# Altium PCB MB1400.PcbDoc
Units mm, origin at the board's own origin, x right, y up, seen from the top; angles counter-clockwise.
Board outline 25 x 36.5 mm, 4 copper layers (Top Layer, Signal Layer 1, Signal Layer 2, Bottom Layer), stack 1.2 mm thick; 32 components, 21 nets, 197 pads, 102 vias.
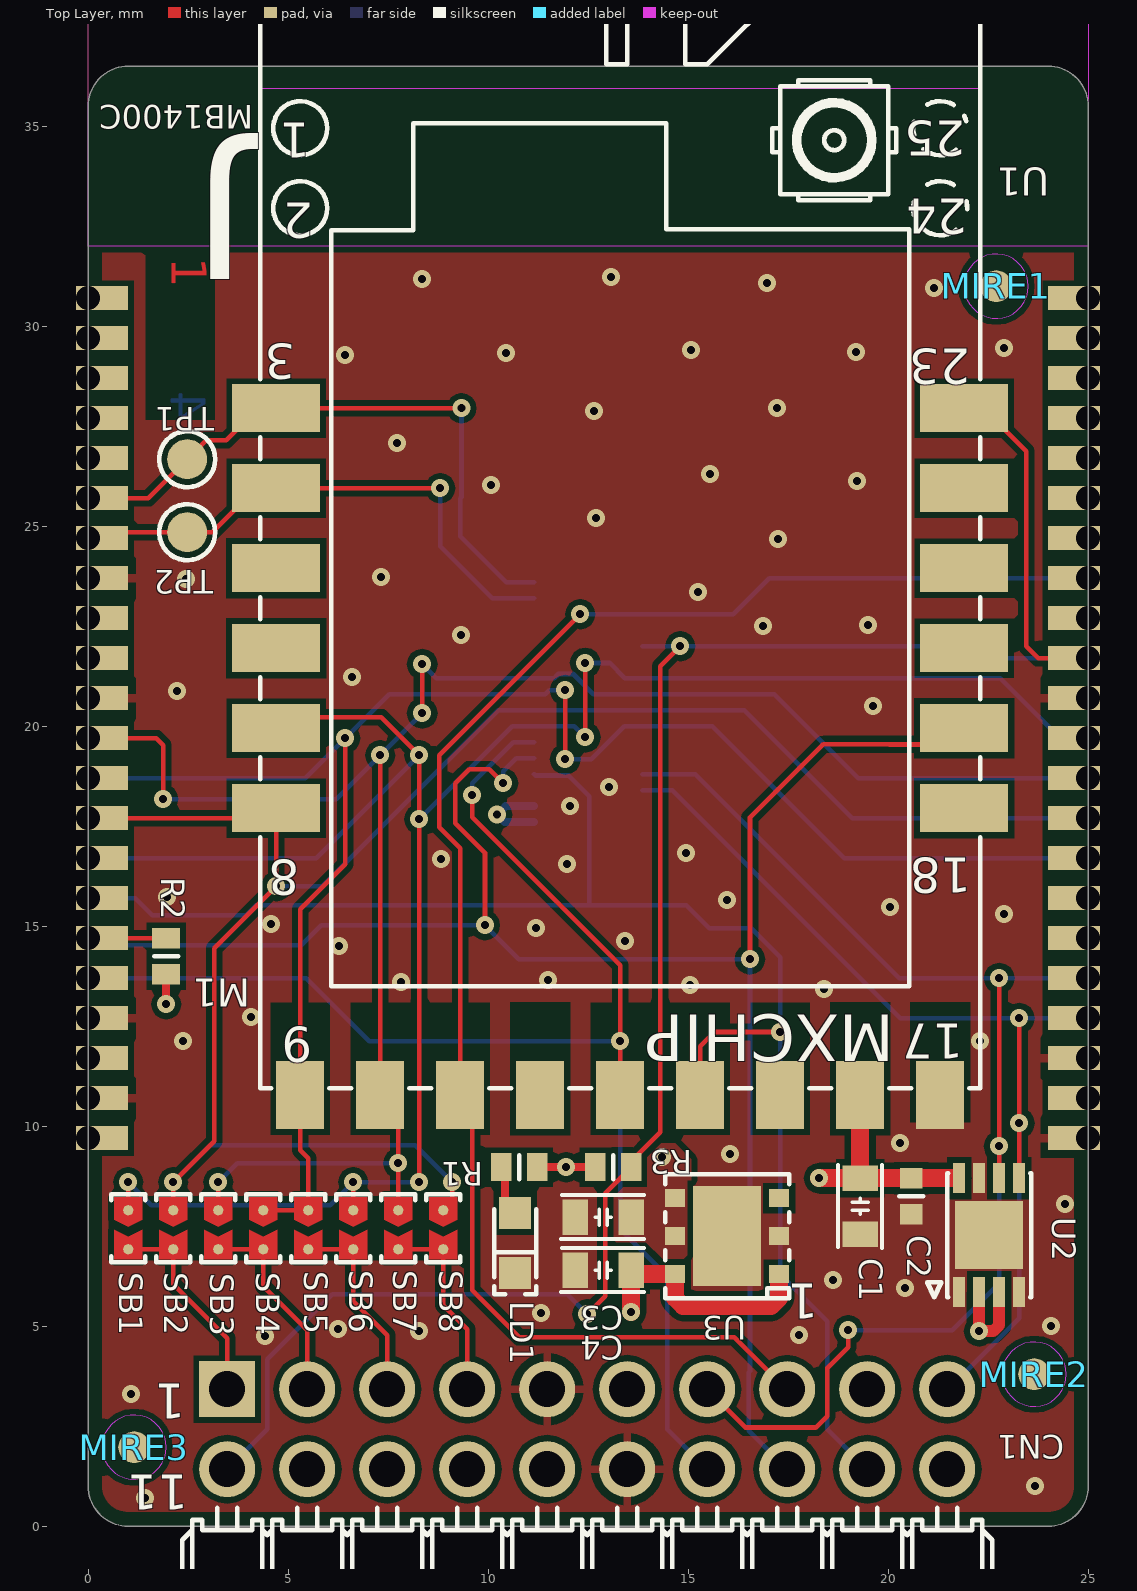
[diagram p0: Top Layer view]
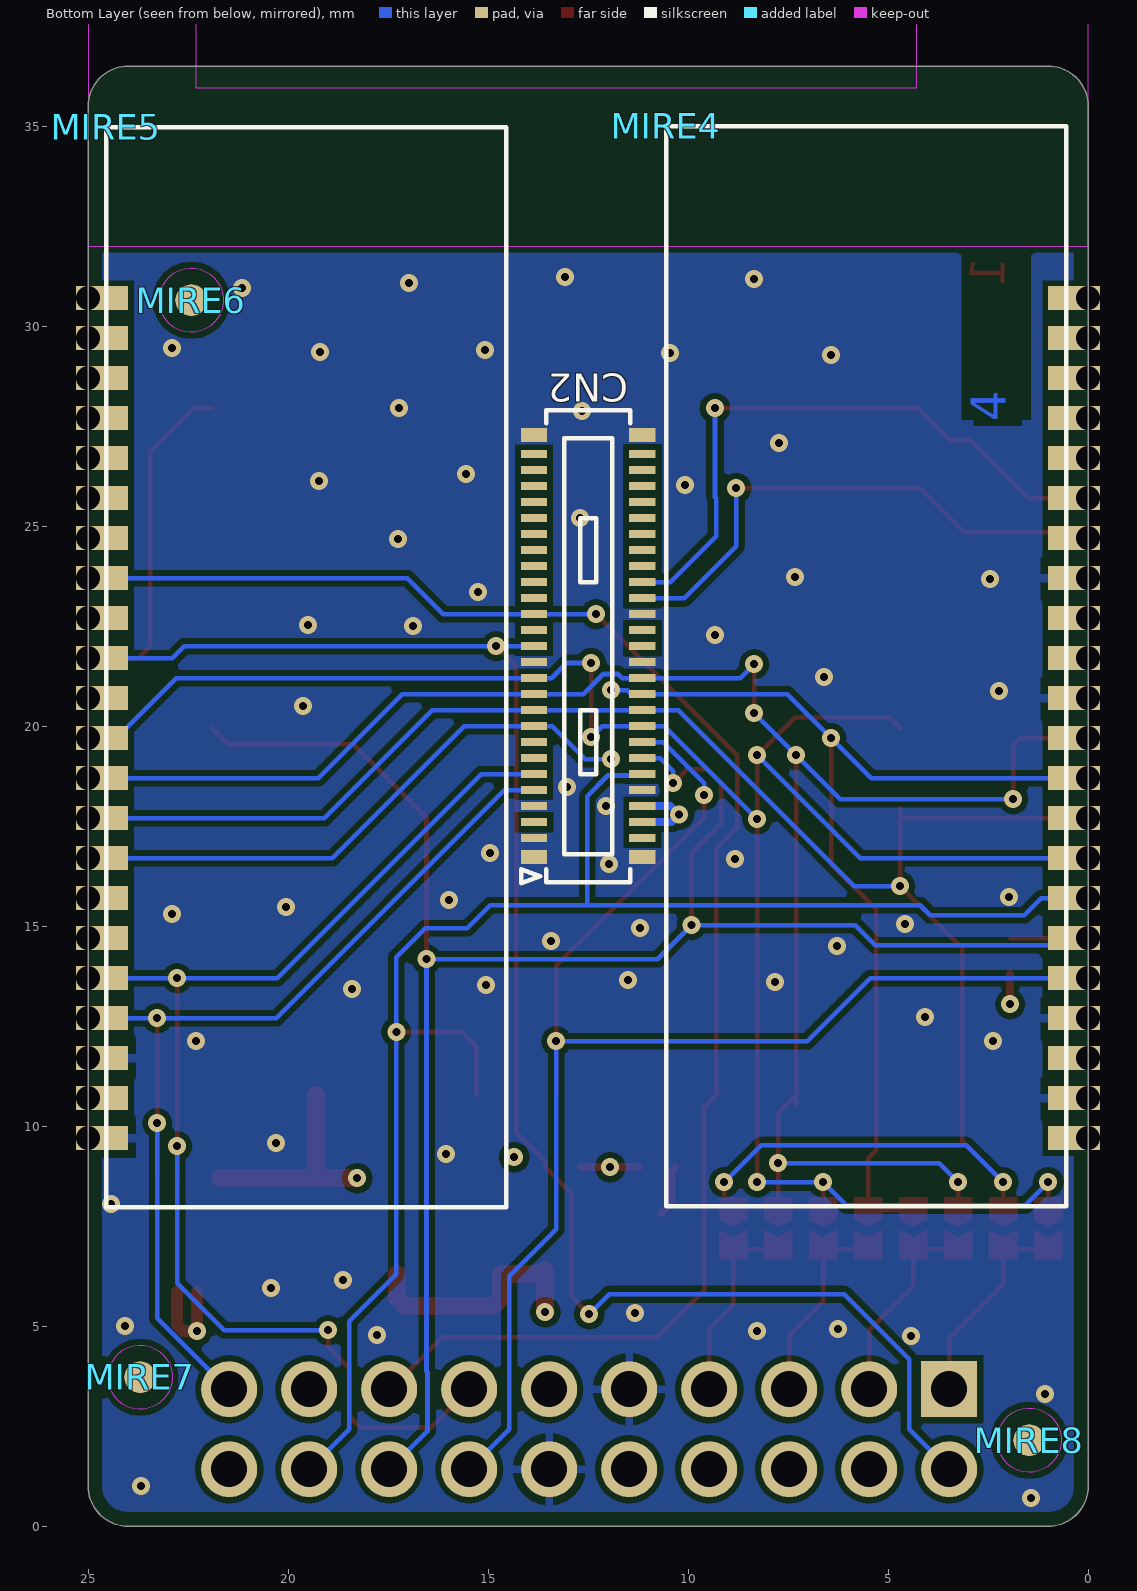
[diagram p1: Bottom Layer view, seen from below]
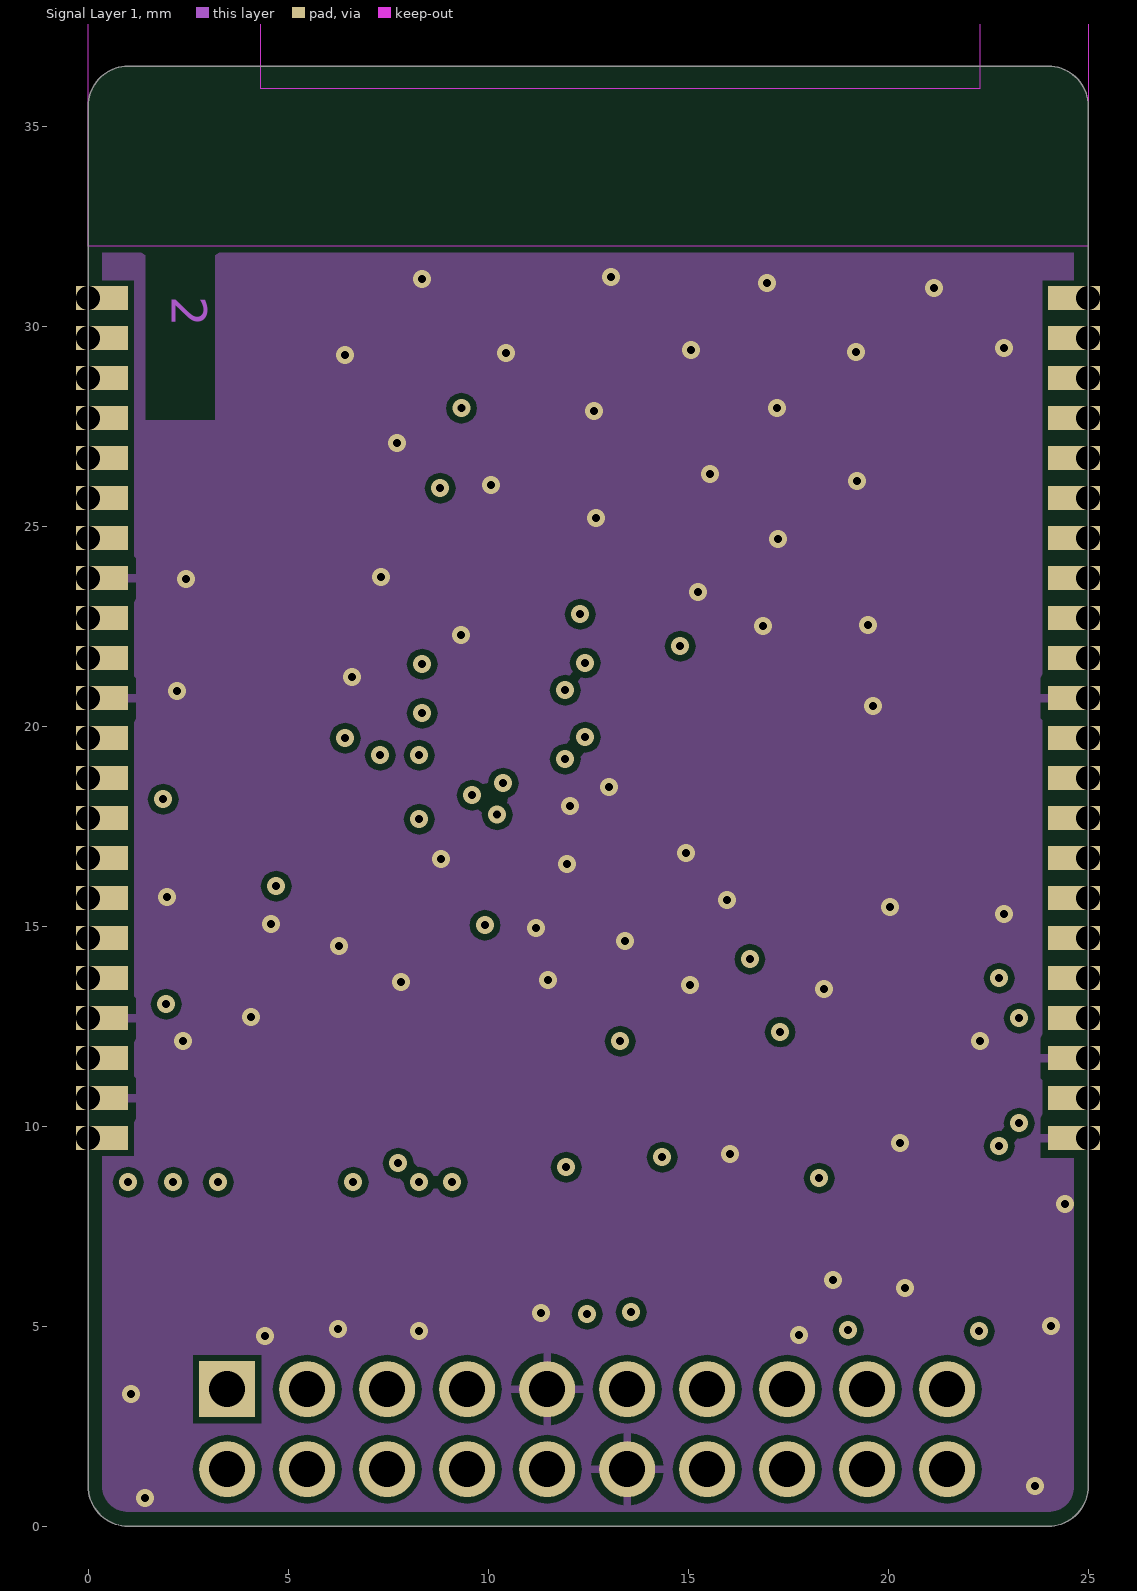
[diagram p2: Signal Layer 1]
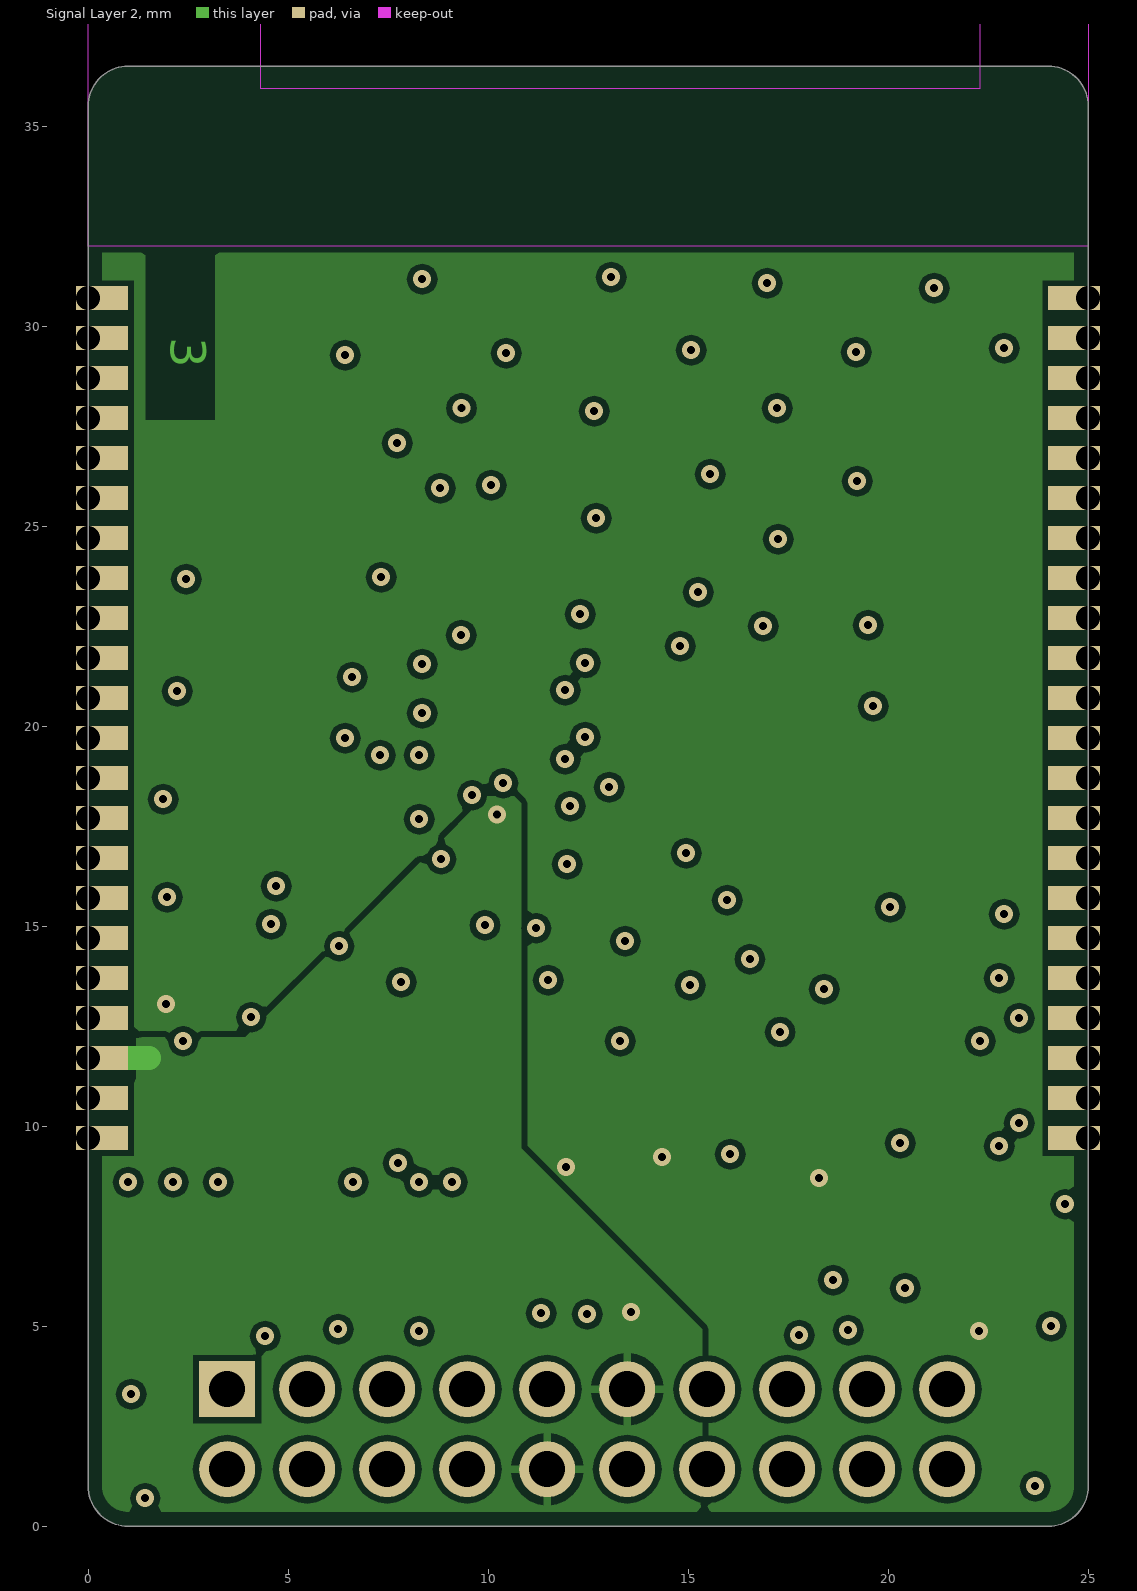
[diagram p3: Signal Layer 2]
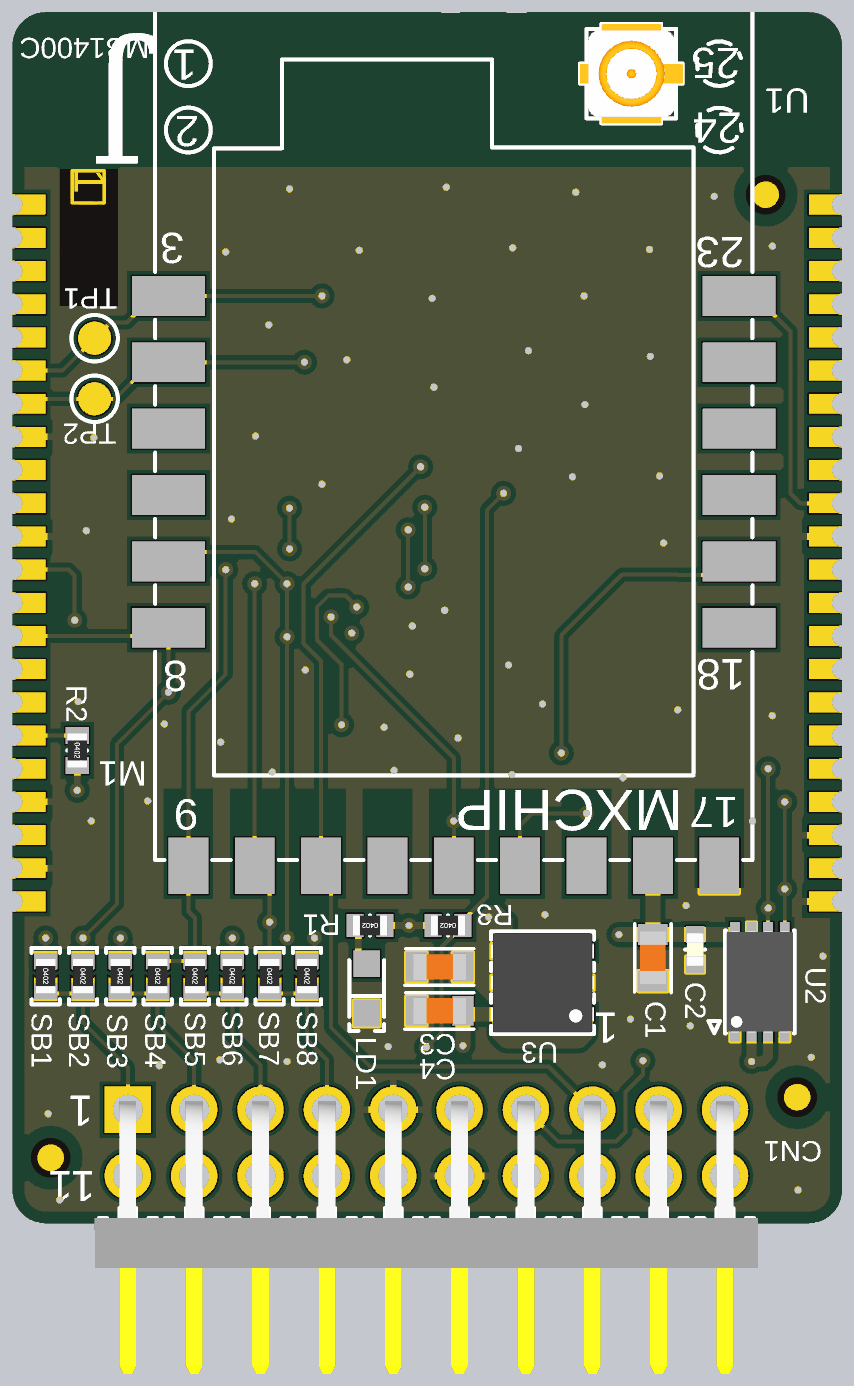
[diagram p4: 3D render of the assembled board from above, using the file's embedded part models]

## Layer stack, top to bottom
Top Solder: solder mask 0.0203, Solder Resist, Dk 3.5
Top Layer: signal copper 0.035
Dielectric 1: core 0.106, FR-4, Dk 4.1
Signal Layer 1: signal copper 0.035
Dielectric 2: prepreg 0.848, Dk 4.25
Signal Layer 2: signal copper 0.035
Dielectric 3: core 0.106, Dk 4.25
Bottom Layer: signal copper 0.035
Bottom Solder: solder mask 0.0203, Solder Resist, Dk 3.5

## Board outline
0,1 0,35.5 cw(c1,35.5) 1,36.5 24,36.5 cw(c24,35.5) 25,35.5 25,1 cw(c24,1) 24,0 1,0 cw(c1,1)

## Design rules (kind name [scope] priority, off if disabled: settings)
BoardOutlineClearance [All] p1: gap=0.4 ignorepadtopadclearanceinfootprint=FALSE except(0.35: Poly-OutlineEdge)
Clearance Clearance_1 [InNetClass('Iso 250µm')] p1: gap=0.25 ignorepadtopadclearanceinfootprint=FALSE except(0: Arc-Hole Track-Hole SMDPad-Hole THPad-Hole Via-Hole Fill-Hole Poly-Hole Region-Hole Text-Hole)
Clearance [All] p2: gap=0.15 ignorepadtopadclearanceinfootprint=FALSE except(0: Arc-Hole Track-Hole SMDPad-Hole THPad-Hole Via-Hole Fill-Hole Poly-Hole Region-Hole Text-Hole; 0.12: Arc-Arc Arc-Track Arc-SMDPad Arc-Via Arc-Text Track-Track Track-SMDPad Track-Via Track-Text SMDPad-Via SMDPad-Text THPad-Via THPad-Text Via-Via Via-Text Fill-Text Poly-Text Region-Text Text-Text; 0.2: Arc-THPad Track-THPad SMDPad-SMDPad SMDPad-THPad THPad-THPad)
ComponentClearance [All] p1 off: gap=0.025 collisioncheckmode=3 verticalgap=2540 showdistances=TRUE
DiffPairsRouting DiffPairsRouting_USB [InDifferentialPairClass('DIFF_USB')] p1: maxlimit=0.12 minlimit=0.12 mostfreqgap=0.12 toplayer_minwidth=0.13 toplayer_maxwidth=0.13 toplayer_prefwidth=0.13 midlayer1_minwidth=0.13 midlayer1_maxwidth=0.13 midlayer1_prefwidth=0.13 midlayer2_minwidth=0.13 midlayer2_maxwidth=0.13 midlayer2_prefwidth=0.13 bottomlayer_minwidth=0.13 bottomlayer_maxwidth=0.13 bottomlayer_prefwidth=0.13 maxuncoupledlength=12.7
FanoutControl Fanout_Default [All] p1: bgadir=Out bgaviamode=Closest fanoutstyle=Auto fanoutdirection=Alternating viagrid=0.025 // Fanout_Default (Default Rule)
HoleSize [All] p1: absolutevalues=TRUE maxlimit=10 minlimit=0.1 maxpercent=80.000 minpercent=20.000
HoleToHoleClearance [All] p1: gap=0.5 allowstackedmicrovias=TRUE
MatchedLengths "MatchedLengths USB diff" [InDifferentialPairClass('All Differential Pairs')] p1: tolerance=0.5 checknetsindiffpair=TRUE checkdiffpairvsdiffpair=FALSE checkxsignals=FALSE checkothers=FALSE
MinimumSolderMaskSliver [All] p1: minsoldermaskwidth=0
PlaneClearance [All] p1: clearance=0.6
PlaneConnect [All] p1: planeconnectstyle=Relief reliefexpansion=0.508 reliefentries=4 reliefconductorwidth=0.254 reliefairgap=0.2
PolygonConnect PolygonConnect_5V [InNet('5V')] p1: thpad.connectstyle=Relief thpad.reliefconductorwidth=0.2 thpad.reliefentries=4 thpad.polygonreliefangle="90 Angle" thpad.airgapwidth=0.2 smdpad.connectstyle=Direct smdpad.reliefconductorwidth=0.254 smdpad.reliefentries=4 smdpad.polygonreliefangle="45 Angle" smdpad.airgapwidth=0.254 via.connectstyle=Direct via.reliefconductorwidth=0.254 via.reliefentries=4 via.polygonreliefangle="45 Angle" via.airgapwidth=0.254
PolygonConnect [All] p2: thpad.connectstyle=Relief thpad.reliefconductorwidth=0.2 thpad.reliefentries=4 thpad.polygonreliefangle="90 Angle" thpad.airgapwidth=0.2 smdpad.connectstyle=Direct smdpad.reliefconductorwidth=0.254 smdpad.reliefentries=4 smdpad.polygonreliefangle="45 Angle" smdpad.airgapwidth=0.254 via.connectstyle=Direct via.reliefconductorwidth=0.254 via.reliefentries=4 via.polygonreliefangle="45 Angle" via.airgapwidth=0.254
RoutingVias [All] p1: holewidth=0.2 width=0.45 viastyle="Through Hole" minholewidth=0.2 minwidth=0.45 maxholewidth=0.2 maxwidth=0.45
SilkToSilkClearance [All] p1: silktosilkclearance=0
SilkToSolderMaskClearance [IsPad] p1: minsilkscreentomaskgap=0 clearancetoexposedcopper=TRUE
SolderMaskExpansion [All] p1: expansion=0.05
Width Width_OSC [InNetClass('Oscillateur')] p1: maxlimit=0.15 minlimit=0.15 preferedwidth=0.15
Width Width_ALIMS [InNetClass('ALIMS')] p2: maxlimit=10 minlimit=0.12 preferedwidth=0.8 minimp=50.000000 maximp=50.000000 favimp=50.000000
Width Width_GND [InNetClass('GND')] p3: maxlimit=10 minlimit=0.12 preferedwidth=0.3 minimp=50.000000 maximp=50.000000 favimp=50.000000
Width [All] p4: maxlimit=10 minlimit=0.12 preferedwidth=0.12 minimp=50.000000 maximp=50.000000 favimp=50.000000
16 further rules are at their usual default settings.

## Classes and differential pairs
polygon class POLY_DIRECT_ALL: NETC906_2_L01_P192

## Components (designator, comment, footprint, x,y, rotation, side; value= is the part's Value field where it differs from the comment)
C1 "Capacitor" C0603 19.3,8 r90 top value=2.2uF
C2 "Capacitor" C0402 20.575,8.25 r90 top value=100nF
C3 "Capacitor" C0603 12.875,7.725 r0 top value=4.7uF
C4 "Capacitor" C0603 12.875,6.4 r0 top value=4.7uF
CN1 "Header 10x2 STMod+" CON_SAMTEC_TMM-110-01-L-D-RA__STMOD+ 12.475,0.155 r0 top
CN2 "DF40C-50DP-0.4V(51)" CON_HRS_DF40C-50DP-0.4V_51 12.5,22 r270 bottom
LD1 "LED_green" LED_0603_VISHAY_VLMTG1300-GS08_GREEN_1A2K_H0P8 10.675,7.075 r270 top value="TRUE GREEN"
M1 "EMW3080(BP)" MOD_WIFI_MXCHIP_EMW3080-BP 13.3,10.95 r0 top
MIRE1 "Comment" MIRE_PLACE_SMD_0P8MM 22.7,31 r0 top
MIRE2 "Comment" MIRE_PLACE_SMD_0P8MM 23.65,3.8 r0 top
MIRE3 "Comment" MIRE_PLACE_SMD_0P8MM 1.15,1.975 r0 top
MIRE4 "Comment" LOGO_ETIQUETTE 10.55,35 r270 bottom locked
MIRE5 "Comment" LOGO_ETIQUETTE 24.55,34.975 r270 bottom
MIRE6 "Comment" MIRE_PLACE_SMD_0P8MM 22.425,30.65 r180 bottom
MIRE7 "Comment" MIRE_PLACE_SMD_0P8MM 23.7,3.725 r180 bottom
MIRE8 "Comment" MIRE_PLACE_SMD_0P8MM 1.475,2.15 r180 bottom
R1 "Resistor" R0402 10.775,8.975 r180 top value=510R
R2 "Resistor" R0402 1.95,14.25 r270 top value=10K
R3 "Resistor" R0402 13.125,8.975 r180 top value=10K
SB1 "SB_ON" SOLDER-BRIDGE_R0402-0R 1,7.45 r270 top
SB2 "SB_ON" SOLDER-BRIDGE_R0402-0R 2.125,7.45 r270 top
SB3 "SB_ON" SOLDER-BRIDGE_R0402-0R 3.25,7.45 r270 top
SB4 "SB_ON" SOLDER-BRIDGE_R0402-0R 4.375,7.45 r270 top
SB5 "SB_ON" SOLDER-BRIDGE_R0402-0R 5.5,7.45 r270 top
SB6 "SB_ON" SOLDER-BRIDGE_R0402-0R 6.625,7.45 r270 top
SB7 "SB_ON" SOLDER-BRIDGE_R0402-0R 7.75,7.45 r270 top
SB8 "SB_ON" SOLDER-BRIDGE_R0402-0R 8.875,7.45 r270 top
TP1 "Test Point" TP_SMD_1MM 2.475,26.675 r90 top
TP2 "Test Point" TP_SMD_1MM 2.475,24.85 r90 top
U1 "WIFI MODULE INTERPOSER" CON_MOD2BOARD_WIFI_MURATA_LBEE5PA1LD 12.5,22 r0 top locked value="WIFI INTERPOSER CONNECTOR"
U2 "M24128-DFMC6TP" ICC_DFN8-EPAD_2X3_P050 22.525,7.275 r180 top value=M24256-DFMC6TG
U3 "ST1L05CPU33R" ICC_DFN6-EPAD_3X3_P095 15.975,7.25 r90 top value="ST1L05CPU33R 3.3V 1.3A"

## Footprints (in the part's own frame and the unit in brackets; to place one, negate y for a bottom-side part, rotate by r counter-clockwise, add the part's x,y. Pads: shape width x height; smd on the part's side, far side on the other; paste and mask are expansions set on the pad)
C0402 [mm]
  rect 0.51x0.56 smd mask+0.05: 1(-0.45,0) 2(0.45,0)
  silkscreen extent 0,-0.3 0,0.3, body extent -0.5,-0.3 0.5,0.3, height 0.4
C0603 [mm]
  rect 0.64x0.89 smd mask+0.05: 1(-0.7,0) 2(0.7,0)
  silkscreen extent -1.05,-0.55 1.02,0.55, body extent -0.9,-0.5 0.9,0.5, height 1.4
CON_HRS_DF40C-50DP-0.4V_51 [mm]
  rect 0.2x0.66 smd mask+0.05: 1(4.8,-1.355) 2(4.4,-1.355) 3(4,-1.355) 4(3.6,-1.355) 5(3.2,-1.355) 6(2.8,-1.355) 7(2.4,-1.355) 8(2,-1.355) 9(1.6,-1.355) 10(1.2,-1.355) 11(0.8,-1.355) 12(0.4,-1.355) 13(0,-1.355) 14(-0.4,-1.355) 15(-0.8,-1.355) 16(-1.2,-1.355) 17(-1.6,-1.355) 18(-2,-1.355) 19(-2.4,-1.355) 20(-2.8,-1.355) 21(-3.2,-1.355) 22(-3.6,-1.355) 23(-4,-1.355) 24(-4.4,-1.355) 25(-4.8,-1.355) 26(-4.8,1.355) 27(-4.4,1.355) 28(-4,1.355) 29(-3.6,1.355) 30(-3.2,1.355) 31(-2.8,1.355) 32(-2.4,1.355) 33(-2,1.355) 34(-1.6,1.355) 35(-1.2,1.355) 36(-0.8,1.355) 37(-0.4,1.355) 38(0,1.355) 39(0.4,1.355) 40(0.8,1.355) 41(1.2,1.355) 42(1.6,1.355) 43(2,1.355) 44(2.4,1.355) 45(2.8,1.355) 46(3.2,1.355) 47(3.6,1.355) 48(4,1.355) 49(4.4,1.355) 50(4.8,1.355)
  rect 0.35x0.66 smd mask+0.05: MT1(5.275,-1.355) MT2(-5.275,-1.355) MT3(-5.275,1.355) MT4(5.275,1.355)
  silkscreen extent -5.9,-1.68 5.92,1.05, body extent -5.9,-1.48 5.9,1.49, height 1.3
CON_MOD2BOARD_WIFI_MURATA_LBEE5PA1LD [mm]
  rect 1.3x0.6 hole 0.6 copper offset -0.35,0 paste-10 mask+0.05: 1(12.5,-12.3) 2(12.5,-11.3) 3(12.5,-10.3) 4(12.5,-9.3) 5(12.5,-8.3) 6(12.5,-7.3) 7(12.5,-6.3) 8(12.5,-5.3) 9(12.5,-4.3) 10(12.5,-3.3) 11(12.5,-2.3) 12(12.5,-1.3) 13(12.5,-0.3) 14(12.5,0.7) 15(12.5,1.7) 16(12.5,2.7) 17(12.5,3.7) 18(12.5,4.7) 19(12.5,5.7) 20(12.5,6.7) 21(12.5,7.7) 22(12.5,8.7)
  rect 1.3x0.6 hole 0.6 copper offset 0.35,0 paste-10 mask+0.05: 23(-12.5,8.7) 24(-12.5,7.7) 25(-12.5,6.7) 26(-12.5,5.7) 27(-12.5,4.7) 28(-12.5,3.7) 29(-12.5,2.7) 30(-12.5,1.7) 31(-12.5,0.7) 32(-12.5,-0.3) 33(-12.5,-1.3) 34(-12.5,-2.3) 35(-12.5,-3.3) 36(-12.5,-4.3) 37(-12.5,-5.3) 38(-12.5,-6.3) 39(-12.5,-7.3) 40(-12.5,-8.3) 41(-12.5,-9.3) 42(-12.5,-10.3) 43(-12.5,-11.3) 44(-12.5,-12.3)
  Keep-Out Layer region: -12.5,20 12.5,20 12.5,10 -12.5,10
CON_SAMTEC_TMM-110-01-L-D-RA__STMOD+ [mm]
  rect 1.4x1.4 hole 0.9 mask+0.05: 1(-9,3.27)
  round 1.4 hole 0.9 mask+0.05: 2(-7,3.27) 3(-5,3.27) 4(-3,3.27) 5(-1,3.27) 6(1,3.27) 7(3,3.27) 8(5,3.27) 9(7,3.27) 10(9,3.27) 11(-9,1.27) 12(-7,1.27) 13(-5,1.27) 14(-3,1.27) 15(-1,1.27) 16(1,1.27) 17(3,1.27) 18(5,1.27) 19(7,1.27) 20(9,1.27)
  silkscreen extent -10.12,-4.7 10.13,0.3, body extent -10.15,-6.35 10.15,3.52, height 4
ICC_DFN6-EPAD_3X3_P095 [mm]
  rect 0.45x0.5 smd mask+0.05: 1(-0.95,-1.3) 2(0,-1.3) 3(0.95,-1.3) 4(0.95,1.3) 5(0,1.3) 6(-0.95,1.3)
  rect 2.5x1.7 smd mask+0.05: EP(0,0)
  silkscreen extent -1.55,-1.55 1.55,1.55, body extent -1.55,-1.55 1.55,1.55, height 1
ICC_DFN8-EPAD_2X3_P050 [mm]
  rect 0.3x0.75 smd mask+0.05: 1(0.75,1.425) 2(0.25,1.425) 3(-0.25,1.425) 4(-0.75,1.425) 5(-0.75,-1.425) 6(-0.25,-1.425) 7(0.25,-1.425) 8(0.75,-1.425)
  rect 1.7x1.7 smd mask+0.05: EP(0,0)
  silkscreen extent -1.05,-1.55 1.55,1.55, body extent -1.05,-1.55 1.05,1.55, height 0.9
LED_0603_VISHAY_VLMTG1300-GS08_GREEN_1A2K_H0P8 [mm]
  rect 0.8x0.8 smd mask+0.05: 1(-0.75,0) 2(0.75,0)
  silkscreen extent -0.85,-0.53 1.28,0.53, body extent -0.85,-0.45 0.85,0.45, height 0.8
LOGO_ETIQUETTE [mm]
  silkscreen extent 0,0 27,10
MIRE_PLACE_SMD_0P8MM [mm]
  round 0.8 smd paste-10 mask+0.2: 1(0,0)
  Top Layer keep-out circle w0.01: c0,0 r0.804
MOD_WIFI_MXCHIP_EMW3080-BP [mm] "MCD-01500"
  rect 2.2x1.2 smd mask+0.05: 3(-8.6,17) 4(-8.6,15) 5(-8.6,13) 6(-8.6,11) 7(-8.6,9) 8(-8.6,7) 18(8.6,7) 19(8.6,9) 20(8.6,11) 21(8.6,13) 22(8.6,15) 23(8.6,17)
  rect 1.2x1.7 smd mask+0.05: 9(-8,-0.175) 10(-6,-0.175) 11(-4,-0.175) 12(-2,-0.175) 13(0,-0.175) 14(2,-0.175) 15(4,-0.175) 16(6,-0.175) 17(8,-0.175)
  Top Layer pour cut-out: -8.75,-0.85 -8.75,2.15 -7.25,2.15 -7.25,-0.85
  Top Layer pour cut-out: -6.75,-0.85 -6.75,2.15 -5.25,2.15 -5.25,-0.85
  Top Layer pour cut-out: -4.75,-0.85 -4.75,2.15 -3.25,2.15 -3.25,-0.85
  Top Layer pour cut-out: -2.75,-0.85 -2.75,2.15 -1.25,2.15 -1.25,-0.85
  Top Layer pour cut-out: -0.75,-0.85 -0.75,2.15 0.75,2.15 0.75,-0.85
  Top Layer pour cut-out: 1.25,-0.85 1.25,2.15 2.75,2.15 2.75,-0.85
  Top Layer pour cut-out: 3.25,-0.85 3.25,2.15 4.75,2.15 4.75,-0.85
  Top Layer pour cut-out: 5.25,-0.85 5.25,2.15 6.75,2.15 6.75,-0.85
  Top Layer pour cut-out: 7.25,-0.85 7.25,2.15 8.75,2.15 8.75,-0.85
  Keep-Out Layer region: 9,33 -9,33 -9,25 9,25
  silkscreen extent -9,0 9,33, body extent -9,0 9,33, height 2.45
R0402 [mm]
  rect 0.51x0.7 smd mask+0.05: 1(-0.45,0) 2(0.45,0)
  silkscreen extent 0,-0.3 0,0.3, body extent -0.52,-0.3 0.52,0.3, height 0.4
SOLDER-BRIDGE_R0402-0R [mil] "MCD-01619"
  round 10 smd paste-393.7: 1(-17.72,0) 2(20.67,0)
  Top Layer region: -30.51,-13.78 -30.51,13.78 -8.37,13.78 -1.48,0 -8.37,-13.78
  Top Layer region: 1.48,13.78 8.37,0 1.48,-13.78 30.51,-13.78 30.51,13.78
  silkscreen extent -33,-17 33,17, body extent -20,-12 20,12, height 14
TP_SMD_1MM [mm]
  round 1 smd paste-10 mask+0.05: 1(0,0)
  silkscreen extent -0.7,-0.7 0.7,0.7

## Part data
C1: library part MCD-00012, "Capacitor, MLCC, 2.2uF, 10V, X5R, 10%, 0603, T=0,8mm", Alternate_Manufacturer=KEMET, Alternate_Manufacturer_Part_Number=C0603C225K8PACTU, Manufacturer=YAGEO, Manufacturer_Part_Number=CC0603KRX5R6BB225, Package=C0603
C2: library part MCD-00006, "Capacitor, MLCC, 100nF, 16V, X7R, 10%, 0402, T=0.5mm", Alternate_Manufacturer=MURATA, Alternate_Manufacturer_Part_Number=GCM155R71C104KA55D, Manufacturer=YAGEO, Manufacturer_Part_Number=CC0402KRX7R7BB104, Package=C0402
C3 C4: library part MCD-00009, "Capacitor, MLCC, 4.7uF, 16V, X5R, 10%, 0603, T=0.8mm", Manufacturer=YAGEO, Manufacturer_Part_Number=CC0603KRX5R7BB475, Package=C0603
CN1: library part MCD-00288, "Header 10x2, 2mm, RA, TH, Height 3.20mm/3.50mm", Alternate_Manufacturer=JIUBABA, Alternate_Manufacturer_Part_Number=PH200210C-07000, Manufacturer=SAMTEC, Manufacturer_Part_Number=TMM-110-01-L-D-RA
CN2: library part MCD-01227, "Header 25x2, 0.4mm pitch, VR, SMT, Height 1.5mm", Manufacturer=HIROSE
LD1: library part MCD-00589, "LED Green, 0603 SMD, Fw Voltage = 2.8V - 3.6V", Alternate_Manufacturer="OSRAM OPTO SEMICONDUCTORS", Alternate_Manufacturer_Part_Number="LG Q396-PS-35", Manufacturer=VISHAY, Manufacturer_Part_Number=VLMTG1300-GS08, Package="LED 0603"
M1: library part MCD-01500, "Wi-Fi module 33x18mm, UART-SPI interface", Manufacturer=MXCHIP
R1: library part MCD-00064, "Resistor,510R,0402,1%,1/16W", Manufacturer=YAGEO, Manufacturer_Part_Number=RC0402FR-07510RL, Package=R0402
R2 R3: library part MCD-00053, "Resistor,10K,0402,1%,1/16W", Manufacturer=YAGEO, Manufacturer_Part_Number=RC0402FR-0710KL, Package=R0402
SB1 SB2 SB3 SB4 SB5 SB6 SB7 SB8: library part MCD-01618, "Solder Bridge 0402 ON", Manufacturer=YAGEO, Manufacturer_Part_Number=RC0402JR-070RL, Package=SB0402
TP1 TP2: library part MCD-00074, "Test Point 1mm", Manufacturer=n/a
U1: library part MCD-01334, "44 pins Generic Interposer Connector (Not Fitted : Footprint only)", Manufacturer=N/A
U2: library part MCD-01871, "I2C Memory 3V3, 256Kbits, 2x3,0.55mm, UFDFPN8", Manufacturer=STMICROELECTRONICS, Manufacturer_Part_Number=M24256-DFMC6TG
U3: library part MCD-01025, "LDO, 3.3V, 1.3A, Very low quiescent current BiCMOS voltage regulator", Manufacturer=STMICROELECTRONICS, Package=DFN6-3x3

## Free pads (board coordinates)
  round 0.508 on Mech16: 1(15.163,-20.715) 1(64.01,-20.715)

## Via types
v1: diameter 0.45, hole 0.2, Top Layer to Bottom Layer, tented both sides, 102 vias

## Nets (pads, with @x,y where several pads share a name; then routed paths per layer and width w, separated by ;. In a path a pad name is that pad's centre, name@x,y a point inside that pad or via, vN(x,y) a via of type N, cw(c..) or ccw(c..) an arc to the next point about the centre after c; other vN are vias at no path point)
5V: C4.2 CN1.6 CN1.15 CN2.48 CN2.49 U1.42 U3.1 U3.6 | length 9.7
  Top Layer w0.45: v1(13.575,5.35) C4.2 13.675,6.3 U3.6 14.675,5.7 14.875,5.5 17.075,5.5 17.275,5.7 U3.1
  Signal Layer 2 w0.6: U1.42 1.525,11.7
  Bottom Layer w0.2: CN2.49 10.412,17.6 v1(10.225,17.788) 10.437,18 CN2.48
BOOT: CN1.18 CN2.45 M1.19 R2.1 U1.39 | length 47.7
  Top Layer w0.12: U1.39@0.46,14.7 R2.1 ; v1(9.918,15.025) 9.918,16.832 9.175,17.575 9.175,18.575 9.525,18.925 10.025,18.925 v1(10.375,18.575) ; v1(16.541,14.175) 16.541,17.716 18.375,19.55 20.027,19.55 20.032,19.545 21.495,19.545 M1.19
  Bottom Layer w0.12: U1.39@0.46,14.7 0.635,14.525 5.325,14.525 5.825,15.025 v1(9.918,15.025) 10.768,14.175 v1(16.541,14.175) 16.541,3.875 16.515,3.849 16.515,2.385 CN1.18 ; v1(10.375,18.575) 10.375,18.875 10.7,19.2 CN2.45
CHIP_EN: CN1.8 CN2.15 M1.11 U1.15 | length 40.2
  Top Layer w0.12: v1(12.3,22.8) 8.775,19.275 8.775,17.475 9.3,16.95 M1.11 9.6,10.475 9.6,5.9 10.775,4.725 16.15,4.725 CN1.8@17.475,3.4
  Bottom Layer w0.12: v1(12.3,22.8) CN2.15 16.125,22.8 17.025,23.7 U1.15@24.54,23.7
ELINK: CN1.11 CN2.13 M1.23 R3.1 U1.13 | length 49.1
  Top Layer w0.12: v1(12.475,5.3) 12.925,5.75 12.925,8.325 R3.1 13.575,9.125 14.3,9.85 14.3,21.5 v1(14.8,22) ; M1.23 22.375,27.95 23.45,26.875 23.45,22 23.75,21.7 U1.13@24.54,21.7
  Bottom Layer w0.12: CN1.11 4.475,2.425 4.475,4.175 6.1,5.8 11.975,5.8 v1(12.475,5.3) ; CN2.13 22.6,22 22.9,21.7 U1.13
FLOW: CN1.17 CN2.44 M1.13 U1.40 | length 36.4
  Top Layer w0.12: v1(9.6,18.275) 9.6,17.725 13.3,14.025 v1(13.3,12.125) M1.13
  Bottom Layer w0.12: U1.40@0.46,13.7 5.45,13.7 7.025,12.125 v1(13.3,12.125) 13.3,7.425 14.475,6.25 14.475,2.425 CN1.17 ; v1(9.6,18.275) 9.6,18.575 10.625,19.6 CN2.44
GND: C1.1 C2.1 C3.1 C4.1 CN1.5 CN1.16 CN2.1 CN2.3 CN2.12 CN2.36 CN2.39 CN2.47 CN2.MT1 CN2.MT2 CN2.MT3 CN2.MT4 LD1.2 M1.17 U1.1 U1.3 U1.12 U1.30 U1.33 U1.41 U1.43 U2.1 U2.4 U2.7 U2.EP U3.2 U3.EP
  other v1: 1.425,0.7 23.675,1 1.075,3.3 4.425,4.75 17.775,4.775 8.275,4.875 6.25,4.925 24.075,5 11.325,5.325 20.425,5.95 18.625,6.15 24.425,8.05 16.05,9.3 20.3,9.575 2.375,12.125 22.3,12.125 4.075,12.725 18.4,13.425 15.05,13.525 7.825,13.6 11.5,13.65 6.275,14.5 13.425,14.625 11.2,14.95 4.575,15.05 22.9,15.3 20.05,15.475 15.975,15.65 1.975,15.725 11.975,16.55 8.825,16.675 14.95,16.825 12.05,18 13.025,18.475 19.625,20.5 2.225,20.875 6.6,21.225 9.325,22.275 16.875,22.5 19.5,22.525 15.25,23.35 2.45,23.675 7.325,23.725 17.25,24.675 12.7,25.2 10.075,26.025 19.225,26.125 15.55,26.3 7.725,27.075 12.65,27.875 17.225,27.95 6.425,29.275 10.45,29.325 19.2,29.35 15.075,29.4 22.9,29.45 21.15,30.95 16.975,31.075 8.35,31.175 13.075,31.225
I2C_SCL: CN1.7 CN2.5 U1.5 U2.6 | length 31.8
  Top Layer w0.12: CN1.7 16.435,2.465 18.19,2.465 18.475,2.75 18.475,3.952 19,4.477 v1(19,4.9) ; U2.6 v1(22.775,9.5) v1(22.775,13.7)
  Bottom Layer w0.12: CN2.5 15.175,18.8 20.275,13.7 U1.5 ; v1(19,4.9) 21.597,4.9 22.775,6.078 v1(22.775,9.5)
I2C_SDA: CN1.10 CN2.4 U1.4 U2.5 | length 24.5
  Top Layer w0.12: U2.5 v1(23.275,10.075) v1(23.275,12.7)
  Bottom Layer w0.12: CN2.4 14.6,18.4 20.3,12.7 U1.4@24.54,12.7 ; CN1.10@21.475,3.4 23.275,5.2 v1(23.275,10.075)
JTCK: CN2.34 M1.3 TP1.1 U1.28 | length 15.8
  Top Layer w0.12: U1.28 1.5,25.7 TP1.1 2.95,27.15 3.45,27.15 4.25,27.95 M1.3 v1(9.33,27.95)
  Bottom Layer w0.12: v1(9.33,27.95) 9.33,25.73 9.3,25.7 9.3,24.75 10.45,23.6 CN2.34
JTMS: CN2.35 M1.4 TP2.1 U1.29 | length 13.7
  Top Layer w0.12: U1.29 0.15,24.85 TP2.1 3.1,24.85 4.2,25.95 M1.4 v1(8.8,25.95)
  Bottom Layer w0.12: v1(8.8,25.95) 8.8,24.5 10.1,23.2 CN2.35
NetCN1_1: CN1.1 SB1.2 SB2.2 | length 5.2
  Top Layer w0.12: SB1.2 SB2.2 2.125,6.05 3.475,4.7 CN1.1
NetCN1_2: CN1.2 SB3.2 SB4.2 | length 5.1
  Top Layer w0.12: SB3.2 SB4.2 4.375,6 5.475,4.9 CN1.2
NetCN1_3: CN1.3 SB5.2 SB6.2 | length 5
  Top Layer w0.12: SB5.2 SB6.2 6.625,5.625 7.475,4.775 CN1.3@7.475,3.4
NetCN1_4: CN1.4 SB7.2 SB8.2 | length 4.9
  Top Layer w0.12: SB7.2 SB8.2 8.875,5.525 9.475,4.925 CN1.4@9.475,3.4
NetLD1_1: LD1.1 R1.2 | length 1.3
  Top Layer w0.2: R1.2 10.425,8.875 10.425,8.075 LD1.1
NOTIFY: CN1.19 CN2.46 M1.14 U1.38 | length 39.5
  Top Layer w0.12: M1.14 15.3,12 15.654,12.354 v1(17.299,12.354)
  Bottom Layer w0.12: U1.38 1.175,15.7 1.6,15.275 3.95,15.275 4.2,15.525 14.95,15.525 15.525,14.95 16.575,14.95 17.299,14.226 17.299,6.301 18.475,5.125 18.475,2.425 CN1.19 ; CN2.46 11.175,18.77 12.005,18.77 12.525,18.25 12.525,15.525
SPI_MISO: CN2.11 CN2.43 M1.7 SB1.1 SB6.1 U1.11 U1.37 | length 52.8
  Top Layer w0.12: SB1.1 v1(1,8.6) ; M1.7 4.975,20.225 7.325,20.225 v1(8.275,19.275) v1(8.275,8.6) ; SB6.1 v1(6.625,8.6) ; v1(12.425,19.725) v1(12.425,21.582)
  Bottom Layer w0.12: U1.37@0.46,16.7 5.7,16.7 v1(8.275,19.275) ; v1(1,8.6) 1.575,8.025 6.05,8.025 v1(6.625,8.6) v1(8.275,8.6) ; v1(8.275,17.675) 10.6,20 CN2.43 12.15,20 v1(12.425,19.725) ; v1(12.425,21.582) 13.036,21.582 13.418,21.2 CN2.11 17.525,21.2 22.8,21.2 24.3,19.7 U1.11@24.54,19.7
SPI_MOSI: CN2.8 CN2.41 M1.9 SB4.1 SB5.1 U1.8 U1.35 | length 42.4
  Top Layer w0.12: SB4.1 SB5.1 5.5,9.2 5.3,9.4 M1.9 5.3,15.425 6.425,16.55 v1(6.425,19.7) ; v1@11.925,19.15 v1(11.925,20.9)
  Bottom Layer w0.12: U1.35@0.46,18.7 5.425,18.7 v1(6.425,19.7) 7.525,20.8 CN2.41 11.425,20.8 11.525,20.9 v1(11.925,20.9) ; v1(11.925,19.175) 12.575,19.175 13.4,20 CN2.8 15.6,20 18.9,16.7 U1.8
SPI_NSS: CN2.9 CN2.42 M1.8 SB2.1 SB8.1 U1.9 U1.36 | length 47.1
  Top Layer w0.12: U1.36@0.46,17.7 M1.8@4.7,17.7 ; SB2.1 v1(2.125,8.6) 3.15,9.625 3.15,14.45 v1(4.7,16) M1.8@4.7,17.7 ; M1.8 M1.8@4.7,17.7 ; SB8.1 9.1,8.125 v1(9.1,8.6)
  Bottom Layer w0.12: v1(2.125,8.6) 3.05,9.525 8.175,9.525 v1(9.1,8.6) ; v1(4.7,16) 5.85,16 10.25,20.4 CN2.42 CN2.9 16.4,20.4 19.1,17.7 U1.9
SPI_SCK: CN2.10 CN2.40 M1.10 SB3.1 SB7.1 U1.10 U1.34 | length 46.5
  Top Layer w0.12: U1.34@0.46,19.7 1.7,19.7 1.875,19.525 v1(1.875,18.175) ; SB3.1 v1(3.25,8.6) ; M1.10@7.3,10.55 M1.10 ; v1(7.3,19.275) M1.10 ; SB7.1 v1(7.75,9.075) 7.75,10.325 M1.10 ; v1(8.35,20.325) v1(8.35,21.55)
  Bottom Layer w0.12: v1(1.875,18.175) 6.2,18.175 v1(7.3,19.275) v1(8.35,20.325) ; v1(3.25,8.6) 3.725,9.075 v1(7.75,9.075) ; v1(8.35,21.55) 8.7,21.2 CN2.40 11.652,21.2 11.757,21.305 12.12,21.305 12.625,20.8 CN2.10 17.15,20.8 19.25,18.7 U1.10
VDD_3V3: C1.2 C2.2 C3.2 M1.16 R1.1 R2.2 R3.2 U2.2 U2.3 U2.8 U3.4 U3.5 | length 10.1
  Top Layer w0.2: v1(1.95,13.05) R2.2 ; R1.1 R3.2
  Top Layer w0.3: U2.2 v1(22.275,4.875) 22.625,4.875 22.775,5.025 U2.3
  Top Layer w0.45: v1(18.275,8.7) C1.2 ; M1.16 C1.2 ; U2.8@21.7,8.7 C2.2 C1.2
  other v1: 11.95,8.975 14.35,9.225
pads on no net: CN1.9 CN1.12 CN1.13 CN1.14 CN1.20 CN2.2 CN2.6 CN2.7 CN2.14 CN2.16 CN2.17 CN2.18 CN2.19 CN2.20 CN2.21 CN2.22 CN2.23 CN2.24 CN2.25 CN2.26 CN2.27 CN2.28 CN2.29 CN2.30 CN2.31 CN2.32 CN2.33 CN2.37 CN2.38 CN2.50 M1.5 M1.6 M1.12 M1.15 M1.18 M1.20 M1.21 M1.22 MIRE1.1 MIRE2.1 MIRE3.1 MIRE6.1 MIRE7.1 MIRE8.1 U1.2 U1.6 U1.7 U1.14 U1.16 U1.17 U1.18 U1.19 U1.20 U1.21 U1.22 U1.23 U1.24 U1.25 U1.26 U1.27 U1.31 U1.32 U1.44 U3.3

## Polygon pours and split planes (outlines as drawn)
5V on Signal Layer 2 "5V" (solid, remove dead copper, pour order 12): 9.95,18.25 10.65,18.25 10.825,18.075 10.825,9.45 15.35,4.925 15.35,0 0,0 0,12.225 3.925,12.225
VDD_3V3 on Signal Layer 2 "VDD_3V3" (solid, pour order 14): 0,0 25,0 25,32 0,32
GND on Top Layer "GND" (solid, remove dead copper, pour order 10): 0,0 25,0 25,32 0,32
VDD_3V3 on Top Layer "VDD_3V3" (solid, remove dead copper, pour order 8): 13.94,7.1 14.358,6.682 14.882,6.682 15.075,6.875 15.075,9.175 14.675,9.575 13.382,9.575 13.1,9.293 13.1,7.2 13.2,7.1
GND on Signal Layer 1 "GND" (solid, pour order 6): 0,32 25,32 25,0 0,0
GND on Bottom Layer "GND" (solid, pour order 18): 0,0 25,0 25,32 0,32

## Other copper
Top Layer:
  text "1" at 1.8,31.725 h1.5 r270
  text ".Layer_Name" at 3.493,-14.367 h3
  text ".GTL" at 45.188,-14.367 h3
Signal Layer 1:
  text "2" at 1.8,30.75 h1.5 r270
  text ".Layer_Name" at 3.493,-14.367 h3
  text ".G1" at 45.188,-14.367 h3
Signal Layer 2:
  text "3" at 1.775,29.725 h1.5 r270
  text ".Layer_Name" at 3.493,-14.367 h3
  text ".G2" at 45.188,-14.367 h3
Bottom Layer:
  text "4" at 1.775,27.625 h1.5 r270
  text ".GBL" at 33.985,-14.399 h3
  text ".Layer_Name" at 75.299,-14.399 h3
Multi-Layer:
  pour cut-out: 1.423,27.65 3.173,27.65 3.173,31.775 1.423,31.775

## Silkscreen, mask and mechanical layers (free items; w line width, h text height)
Top Overlay:
  text "MB1400C" at 4.125,35.725 h1 r180
  text "J" at 4,35 h6 r180
  text ".Layer_Name" at 3.493,-14.367 h3
  text ".GTO" at 45.188,-14.367 h3
Bottom Overlay:
  text ".GBO" at 33.985,-14.399 h3
  text ".Layer_Name" at 75.299,-14.399 h3
Top Paste:
  text ".Layer_Name" at 3.493,-14.367 h3
  text ".GTP" at 45.188,-14.367 h3
Bottom Paste:
  text ".GBP" at 33.985,-14.399 h3
  text ".Layer_Name" at 75.299,-14.399 h3
Top Solder:
  region: 3.173,31.775 1.423,31.775 1.423,27.65 3.173,27.65
  text ".Layer_Name" at 3.493,-14.367 h3
  text ".GTS" at 45.188,-14.367 h3
Bottom Solder:
  region: 3.173,31.775 1.423,31.775 1.423,27.65 3.173,27.65
  text ".GBS" at 33.985,-14.399 h3
  text ".Layer_Name" at 75.299,-14.399 h3
M1-Board Shape:
  the board outline again, w0.1
M2-Board Dimensions:
  text ".Layer_Name" at 3.493,-14.367 h3
  text ".GM2" at 45.188,-14.367 h3
M14-Top Assembly:
  text ".Layer_Name" at 3.493,-14.367 h3
  text ".GM14" at 45.188,-14.367 h3
M15-Bottom Assembly:
  text ".GM15" at 33.985,-14.399 h3
  text ".Layer_Name" at 75.299,-14.399 h3
Drill Drawing:
  drawing of 318 lines, arcs and shapes, not listed
  text "PCB SPECIFICATIONS :" at 60.175,85.9 h3
  text "A.   MATERIAL :" at 60.175,81.9 h3
  text "FR-4" at 98.675,81.9 h3
  text "TG-170" at 115.175,81.9 h3
  text "X  TG-150" at 133.425,81.9 h3
  text "TG-140" at 149.425,81.9 h3
  text "B.   MATERIAL FAMILY :" at 60.175,78.9 h3
  text "N/A" at 98.675,78.9 h3
  text "C.   SOLDERMASK COLOR :" at 60.175,75.9 h3
  text "GREEN" at 98.675,75.9 h3
  text "X  BLUE" at 115.175,75.9 h3
  text "RED" at 133.425,75.9 h3
  text "BLACK" at 149.425,75.9 h3
  text "D.   SILKSCREEN COLOR :" at 60.175,72.9 h3
  text "X  WHITE" at 98.675,72.9 h3
  text "YELLOW" at 115.175,72.9 h3
  text "BLACK" at 133.425,72.9 h3
  text "E.   SURFACE FINISH :" at 60.175,69.9 h3
  text "X  ENIG" at 98.675,69.9 h3
  text "IMMERSION SILVER" at 115.175,69.9 h3
  text "IMMERSION TIN" at 149.425,69.9 h3
  text "HASL" at 98.675,66.9 h3
  text "HASL (PB-FREE)" at 115.175,66.9 h3
  text "GOLDEN FINGER" at 149.425,66.9 h3
  text "F.   IMPEDANCE CONTROL :" at 60.175,63.9 h3
  text "NO" at 98.675,63.9 h3
  text "X  YES  (SEE IMPEDANCE TABLE FOR DETAIL INFORMATION)" at 115.175,63.9 h3
  text "G.   THROUGH VIA :" at 60.175,60.9 h3
  text "PLUG THE VIAS WHICH ARE COVERED WITH SOLDERMASK ONE OR TWO SIDE." at 98.675,60.9 h3
  text "PLUG MATERIAL :" at 98.675,57.9 h3
  text "X  SOLDERMASK" at 124.175,57.9 h3
  text "NON-CONDUCTIVE EPOXY." at 149.425,57.9 h3
  text "H.   STACK-UP :" at 60.175,54.9 h3
  text "SEE LAYER STACK-UP SEQUENCE FOR OVERALL THICKNESS." at 98.675,54.9 h3
  text "Layer" at 61.304,45.775 h2
  text "Name" at 69.678,45.775 h2
  text "Material" at 85.875,45.775 h2
  text "Thickness" at 100.429,45.775 h2
  text "Constant" at 112.384,45.775 h2
  text "Board Layer Stack" at 123.448,45.775 h2
  text "MINIMUN PARAMETERS" at 145.25,43.5 h3
  text "1" at 61.304,41.775 h2
  text "Top Overlay" at 69.678,41.775 h2
  text "DEFAULT" at 145.25,38 h3
  text "2" at 61.304,37.775 h2
  text "Top Solder" at 69.678,37.775 h2
  text "Solder Resist" at 85.875,37.775 h2
  text "0,020mm" at 100.429,37.775 h2
  text "3,5" at 112.384,37.775 h2
  text "3" at 61.304,33.775 h2
  text "Top Layer" at 69.678,33.775 h2
  text "Copper" at 85.875,33.775 h2
  text "0,035mm" at 100.429,33.775 h2
  text "TRACKS : 0.120mm           / GAPS : 0.120mm" at 145.25,32.25 h3
  text "4" at 61.304,29.775 h2
  text "Dielectric 1" at 69.678,29.775 h2
  text "FR-4" at 85.875,29.775 h2
  text "0,106mm" at 100.429,29.775 h2
  text "4,1" at 112.384,29.775 h2
  text "5" at 61.304,25.775 h2
  text "Signal Layer 1" at 69.678,25.775 h2
  text "Copper" at 85.875,25.775 h2
  text "0,035mm" at 100.429,25.775 h2
  text "6" at 61.304,21.775 h2
  text "Dielectric 2" at 69.678,21.775 h2
  text "0,848mm" at 100.429,21.775 h2
  text "4,25" at 112.384,21.775 h2
  text "7" at 61.304,17.775 h2
  text "Signal Layer 2" at 69.678,17.775 h2
  text "Copper" at 85.875,17.775 h2
  text "0,035mm" at 100.429,17.775 h2
  text "8" at 61.304,13.775 h2
  text "Dielectric 3" at 69.678,13.775 h2
  text "0,106mm" at 100.429,13.775 h2
  text "4,25" at 112.384,13.775 h2
  text "9" at 61.304,9.775 h2
  text "Bottom Layer" at 69.678,9.775 h2
  text "Copper" at 85.875,9.775 h2
  text "0,035mm" at 100.429,9.775 h2
  text "10" at 61.304,5.775 h2
  text "Bottom Solder" at 69.678,5.775 h2
  text "Solder Resist" at 85.875,5.775 h2
  text "0,020mm" at 100.429,5.775 h2
  text "3,5" at 112.384,5.775 h2
  text "11" at 61.304,1.775 h2
  text "Bottom Overlay" at 69.678,1.775 h2
  text ".Layer_Name" at 3.493,-14.367 h3
  text ".DRL" at 45.188,-14.367 h3
  text "Symbol" at 61.381,-31.7 h2.72
  text "Count" at 72.047,-31.7 h2.72
  text "Hole Size" at 82.978,-31.7 h2.72
  text "Plated" at 103.711,-31.7 h2.72
  text "Hole Type" at 113.075,-31.7 h2.72
  text "Drill Layer Pair" at 126.707,-31.7 h2.72
  text "Via/Pad" at 152.549,-31.7 h2.72
  text "Hole Length" at 163.72,-31.7 h2.72
  text "Routed Path Length" at 179.319,-31.7 h2.72
  text "102" at 72.047,-36.4 h2.27
  text "0,200mm (7,87mil)" at 82.978,-36.4 h2.27
  text "PTH" at 103.711,-36.4 h2.27
  text "Round" at 113.075,-36.4 h2.27
  text "Top Layer - Bottom Layer" at 126.707,-36.4 h2.27
  text "Via" at 152.549,-36.4 h2.27
  text "-" at 163.72,-36.4 h2.27
  text "-" at 179.319,-36.4 h2.27
  text "44" at 72.047,-41.1 h2.27
  text "0,600mm (23,62mil)" at 82.978,-41.1 h2.27
  text "PTH" at 103.711,-41.1 h2.27
  text "Round" at 113.075,-41.1 h2.27
  text "Top Layer - Bottom Layer" at 126.707,-41.1 h2.27
  text "Pad" at 152.549,-41.1 h2.27
  text "-" at 163.72,-41.1 h2.27
  text "-" at 179.319,-41.1 h2.27
  text "20" at 72.047,-45.8 h2.27
  text "0,900mm (35,43mil)" at 82.978,-45.8 h2.27
  text "PTH" at 103.711,-45.8 h2.27
  text "Round" at 113.075,-45.8 h2.27
  text "Top Layer - Bottom Layer" at 126.707,-45.8 h2.27
  text "Pad" at 152.549,-45.8 h2.27
  text "-" at 163.72,-45.8 h2.27
  text "-" at 179.319,-45.8 h2.27
  text "166 Total" at 72.047,-50.5 h2.27
M20-Top Sheet Box:
  circle w0.254: c81.497,-21.088 r1.3
  region: 81.023,-13.851 65.495,-13.851 64.801,-15.627 63.59,-16.852 62.193,-14.992 62.193,-13.341 63.336,-11.944 64.772,-11.565 81.023,-11.565
  region: 67.019,-22.181 56.263,-22.181 57.257,-19.688 65.114,-19.688 65.563,-18.929 67.772,-21.477
  lines w0.254: 57.257,-19.688 66.049,-19.688 62.982,-16.15 cw(c64.786,-14.206) 65.026,-11.565 81.79,-11.565 81.028,-13.851 ; 60.57,-11.318 cw(c62.997,-12.289) 63.233,-9.686 ; 60.61,-11.286 56.263,-22.181 75.586,-22.181 ccw(c75.835,-19.446) 78.384,-20.466 ; 62.349,-15.22 67.772,-21.477 ; 62.603,-15.22 67.908,-21.342 ; 62.603,-14.966 67.908,-21.088 ; 62.701,-13.851 75.694,-13.851 ; 62.73,-14.839 68.035,-20.961 ; 62.857,-14.712 68.162,-20.834 ; 62.984,-14.585 68.289,-20.707 ; 63.111,-14.458 68.416,-20.58 ; 63.166,-12.506 68.471,-18.627 ; 63.234,-9.686 82.684,-9.686 78.385,-20.464 ; 63.238,-14.331 68.489,-20.39 ; 63.238,-14.077 68.543,-20.199 ; 63.238,-13.823 68.543,-19.945 ; 63.238,-12.934 68.543,-19.056 ; 63.365,-13.696 68.67,-19.818 ; 63.365,-13.315 68.67,-19.437 ; 64.737,-19.701 ccw(c64.842,-19.166) 65.14,-18.709 ; 65.824,-13.838 ccw(c65.798,-14.405) 65.467,-14.867 67.832,-17.596 cw(c66.028,-19.54) 66.761,-22.089 ; 72.105,-21.977 74.994,-13.597 ; 72.327,-21.927 75.196,-13.606 ; 72.454,-21.927 75.323,-13.606 ; 72.708,-21.927 75.577,-13.606 ; 72.962,-21.927 75.831,-13.606 ; 73.216,-21.927 76.085,-13.606 ; 73.47,-21.927 76.339,-13.606 ; 73.724,-21.927 76.593,-13.606 ; 73.978,-21.927 76.847,-13.606 ; 74.232,-21.927 77.101,-13.606 ; 74.441,-21.977 77.33,-13.597 ; 77.33,-13.851 81.023,-13.851 ; 80.354,-13.849 81.116,-11.563 ; 80.52,-13.851 81.282,-11.565 ; 80.774,-13.851 81.536,-11.565
  lines w0.3: -5.507,-26.067 84.493,-26.067 84.493,-6.067 -5.507,-6.067 ; -5.507,-21.067 54.493,-21.067 ; -5.507,-16.067 54.493,-16.067 ; -5.507,-11.067 54.493,-11.067 ; -5.507,-26.067 -5.507,-6.067 ; 34.493,-26.067 34.493,-11.067 ; 54.493,-26.067 54.493,-6.067 ; 72.105,-21.977 74.441,-21.977
  text "Project: '.Board_Name'" at -4.507,-9.283 h3
  text "Layer:" at -4.507,-14.367 h3
  text "Gerber:" at 35.482,-14.367 h3
  text "Variant: '.VariantName'" at -4.507,-19.367 h3
  text "Ref: MB1400" at 35.609,-19.367 h3
  text "R" at 80.989,-21.85 h1.52
  text "Date: 6-APR-2020" at -4.507,-24.367 h3
  text "Rev: '.Board_PCB_Revision'" at 35.552,-24.367 h3
M21-Bottom Sheet Box:
  circle w0.254: c-2.324,-21.088 r1.3
  region: 12.154,-22.181 22.91,-22.181 21.917,-19.688 14.059,-19.688 13.61,-18.929 11.402,-21.477
  region: -1.849,-13.851 13.678,-13.851 14.372,-15.627 15.583,-16.852 16.98,-14.992 16.98,-13.341 15.837,-11.944 14.401,-11.565 -1.849,-11.565
  lines w0.254: -2.363,-11.565 -1.601,-13.851 ; -2.109,-11.565 -1.347,-13.851 ; -1.943,-11.563 -1.181,-13.849 ; -1.855,-13.851 -2.617,-11.565 14.147,-11.565 cw(c14.387,-14.206) 16.191,-16.15 13.125,-19.688 21.917,-19.688 ; -1.849,-13.851 1.843,-13.851 ; 0.788,-20.464 -3.511,-9.686 15.939,-9.686 ; 0.789,-20.466 ccw(c3.339,-19.446) 3.587,-22.181 22.91,-22.181 18.564,-11.286 ; 1.843,-13.597 4.732,-21.977 ; 2.072,-13.606 4.941,-21.927 ; 2.326,-13.606 5.195,-21.927 ; 2.58,-13.606 5.449,-21.927 ; 2.834,-13.606 5.703,-21.927 ; 3.088,-13.606 5.957,-21.927 ; 3.342,-13.606 6.211,-21.927 ; 3.479,-13.851 16.472,-13.851 ; 3.596,-13.606 6.465,-21.927 ; 3.85,-13.606 6.719,-21.927 ; 3.977,-13.606 6.846,-21.927 ; 4.179,-13.597 7.068,-21.977 ; 10.503,-19.818 15.808,-13.696 ; 10.503,-19.437 15.808,-13.315 ; 10.63,-20.199 15.935,-14.077 ; 10.63,-19.945 15.935,-13.823 ; 10.63,-19.056 15.935,-12.934 ; 10.684,-20.39 15.935,-14.331 ; 10.702,-18.627 16.007,-12.506 ; 10.757,-20.58 16.062,-14.458 ; 10.884,-20.707 16.189,-14.585 ; 11.011,-20.834 16.316,-14.712 ; 11.138,-20.961 16.443,-14.839 ; 11.265,-21.342 16.57,-15.22 ; 11.265,-21.088 16.57,-14.966 ; 11.402,-21.477 16.824,-15.22 ; 12.412,-22.089 cw(c13.145,-19.54) 11.341,-17.596 13.706,-14.867 ccw(c13.376,-14.405) 13.35,-13.838 ; 14.033,-18.709 ccw(c14.331,-19.166) 14.436,-19.701 ; 15.94,-9.686 cw(c16.177,-12.289) 18.603,-11.318
  lines w0.3: 4.732,-21.977 7.068,-21.977 ; 24.493,-26.067 24.493,-6.067 ; 24.493,-21.067 84.493,-21.067 ; 24.493,-16.067 84.493,-16.067 ; 24.493,-11.067 84.493,-11.067 ; 44.493,-26.067 44.493,-11.067 ; -5.507,-26.067 84.493,-26.067 84.493,-6.067 -5.507,-6.067 -5.507,-26.067
  text "Project: '.Board_Name'" at 83.299,-9.283 h3
  text "Gerber:" at 43.31,-14.367 h3
  text "Layer:" at 83.299,-14.367 h3
  text "Ref: MB1400" at 43.31,-19.367 h3
  text "Variant: '.VariantName'" at 83.299,-19.367 h3
  text "R" at -1.816,-21.85 h1.52
  text "Rev: '.Board_PCB_Revision'" at 43.367,-24.367 h3
  text "Date: 6-APR-2020" at 83.299,-24.367 h3

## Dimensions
1,0 to 1,36.5 on M2-Board Dimensions
0,35.5 to 25,35.5 on M2-Board Dimensions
